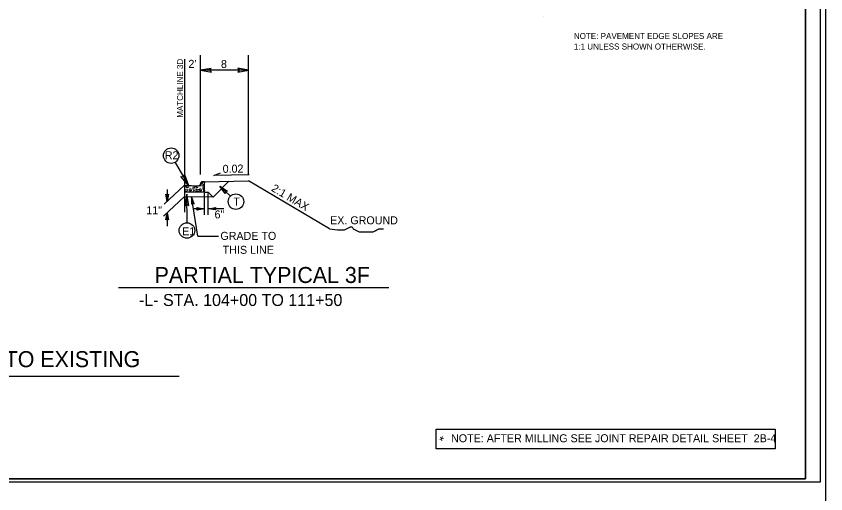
# Model space of a CAD drawing. Extents: x 2320980 to 2456309, y 595047 to 606177.
# Drawn here: x 2455910.9 to 2456045.5, y 596743.6 to 596823 of the extents above; entities that cross this region are included whole.
import ezdxf

# ---------------------------------------------------------------- set-up
doc = ezdxf.new("R2010")
doc.units = 0
for name, color, linetype in [('Matchline', 7, 'Continuous'), ('Matchline Text', 7, 'Continuous'), ('Old_Level_1', 7, 'Continuous'), ('Old_Level_2', 7, 'Continuous'), ('Old_Level_20', 7, 'Continuous'), ('Old_Level_21', 7, 'Continuous'), ('Old_Level_3', 7, 'Continuous'), ('Prop Dimension', 7, 'Continuous'), ('Prop Dimension Text', 7, 'Continuous'), ('Prop Pavement Schedule Description CELL', 7, 'Continuous'), ('Prop Terminator CELL', 7, 'Continuous'), ('Sheet Plan CELL', 7, 'Continuous'), ('Sheet Plot Border Inside CELL', 7, 'Continuous'), ('Sheet Plot Border Outside CELL', 7, 'Continuous'), ('Typical Berm CELL', 7, 'Continuous'), ('Typical Curb CELL', 7, 'Continuous'), ('Typical Hinge Slope Arterial CELL', 7, 'Continuous'), ('Typical ID Circle CELL', 7, 'Continuous'), ('Typical Pavement Slope CELL', 7, 'Continuous'), ('Typical Pavement Slope Information CELL', 7, 'Continuous'), ('Typical Terminator CELL', 7, 'Continuous')]:
    doc.layers.add(name, color=color, linetype=linetype)

msp = doc.modelspace()

# ---------------------------------------------------------------- linework, layer by layer
at = {"layer": 'Matchline'}
msp.add_line((2455938.91, 596815.85), (2455938.91, 596790.41), dxfattribs=at)
at = {"layer": 'Old_Level_21'}
for p, q in [((2455941.57, 596812.79), (2455941.57, 596816.52)), ((2455949.57, 596796.71), (2455949.57, 596816.52)), ((2455949.57, 596814.03), (2455941.57, 596814.03)), ((2455941.57, 596796.71), (2455941.57, 596812.79)), ((2455963.04, 596787.65), (2455949.57, 596795.62)), ((2455941.13, 596786.4), (2455940.1, 596793.02)), ((2455942.24, 596789.98), (2455942.24, 596793.57)), ((2455942.87, 596789.98), (2455942.87, 596793.53)), ((2455941.13, 596786.4), (2455944.57, 596786.4))]:
    msp.add_line(p, q, dxfattribs=at)
msp.add_lwpolyline([(2455980.74, 596754.3), (2456037.11, 596754.3), (2456037.11, 596751.08), (2455980.74, 596751.08)], close=True, dxfattribs=at)
at = {"layer": 'Old_Level_3'}
for p, q in [((2455927.96, 596777.91), (2455972.88, 596777.91)), ((2455830.01, 596763.14), (2455938.01, 596763.14))]:
    msp.add_line(p, q, dxfattribs=at)
at = {"layer": 'Prop Dimension'}
for p, q in [((2455938.91, 596794.91), (2455935.54, 596791.73)), ((2455938.92, 596793.04), (2455935.41, 596789.73)), ((2455936.04, 596794.2), (2455936.04, 596792.2)), ((2455936.04, 596790.33), (2455936.04, 596788.07))]:
    msp.add_line(p, q, dxfattribs=at)
at = {"layer": 'Prop Dimension Text'}
for p, q in [((2455946.54, 596793.07), (2455944.78, 596794.75)), ((2455942.24, 596791), (2455940.35, 596791)), ((2455945.43, 596791), (2455942.87, 596791))]:
    msp.add_line(p, q, dxfattribs=at)
msp.add_lwpolyline([(2455949.64, 596796.65), (2455943.78, 596796.49), (2455944.92, 596796.98)], dxfattribs=at)
for centre in [(2455936.7, 596799.82), (2455947.47, 596792.17), (2455939.32, 596787.37)]:
    msp.add_circle(centre, 1.29, dxfattribs=at)
at = {"layer": 'Prop Pavement Schedule Description CELL'}
msp.add_line((2455998.64, 596823.01), (2455998.64, 596823.01), dxfattribs=at)
at = {"layer": 'Prop Terminator CELL'}
for points in [[(2455936.24, 596793.4), (2455936.04, 596792.2), (2455935.82, 596793.41), (2455936.04, 596793.25)], [(2455935.83, 596789.13), (2455936.04, 596790.33), (2455936.25, 596789.12), (2455936.04, 596789.28)]]:
    msp.add_lwpolyline(points, close=True, dxfattribs=at)
at = {"layer": 'Sheet Plan CELL'}
for points in [[(2456042.11, 596956.08), (2455742.1, 596956.08), (2455742.1, 596746.08), (2456042.11, 596746.08)], [(2455742.1, 596746.08), (2455742.1, 596956.07), (2456002.1, 596956.08), (2456002.1, 596926.07), (2456042.11, 596926.06), (2456042.11, 596746.08)]]:
    msp.add_lwpolyline(points, close=True, dxfattribs=at)
at = {"layer": 'Sheet Plot Border Inside CELL'}
msp.add_lwpolyline([(2455711.41, 596745.57), (2456044.6, 596745.58), (2456044.61, 596956.57), (2455711.41, 596956.57)], close=True, dxfattribs=at)
at = {"layer": 'Sheet Plot Border Outside CELL'}
msp.add_lwpolyline([(2455708.81, 596741.57), (2456045.51, 596741.57), (2456045.51, 596960.57), (2455708.81, 596960.57)], close=True, dxfattribs=at)
at = {"layer": 'Typical Berm CELL'}
for p, q in [((2455942.24, 596795.47), (2455949.57, 596795.62)), ((2455942.24, 596793.75), (2455942.86, 596793.75))]:
    msp.add_line(p, q, dxfattribs=at)
at = {"layer": 'Typical Curb CELL'}
for p, q in [((2455938.91, 596794.91), (2455941.24, 596794.82)), ((2455939.26, 596794.46), (2455939.38, 596794.62)), ((2455939.42, 596794.46), (2455939.26, 596794.46)), ((2455939.38, 596794.62), (2455939.42, 596794.46)), ((2455940.28, 596794.39), (2455940.36, 596794.54)), ((2455940.5, 596794.44), (2455940.28, 596794.39)), ((2455940.36, 596794.54), (2455940.5, 596794.44)), ((2455940.92, 596794.46), (2455941.04, 596794.62)), ((2455941.08, 596794.46), (2455940.92, 596794.46)), ((2455941.04, 596794.62), (2455941.08, 596794.46)), ((2455941.57, 596795.13), (2455941.57, 596795.15)), ((2455941.69, 596795.12), (2455941.77, 596795.27)), ((2455941.91, 596795.17), (2455941.69, 596795.12)), ((2455941.77, 596795.27), (2455941.91, 596795.17)), ((2455942.24, 596795.47), (2455941.89, 596795.47)), ((2455941.94, 596794.39), (2455942.02, 596794.54)), ((2455942.16, 596794.44), (2455941.94, 596794.39)), ((2455941.99, 596795.02), (2455942.01, 596794.9)), ((2455942.19, 596794.96), (2455941.99, 596795.02)), ((2455942.01, 596794.9), (2455942.19, 596794.96)), ((2455942.02, 596794.54), (2455942.16, 596794.44)), ((2455942.24, 596793.75), (2455942.24, 596795.47)), ((2455942.24, 596793.75), (2455938.91, 596793.75)), ((2455939.05, 596793.86), (2455939.16, 596794.01)), ((2455939.21, 596793.86), (2455939.05, 596793.86)), ((2455939.16, 596794.01), (2455939.21, 596793.86)), ((2455939.84, 596793.95), (2455939.95, 596794.11)), ((2455940, 596793.96), (2455939.84, 596793.95)), ((2455939.95, 596794.11), (2455940, 596793.96)), ((2455940.86, 596793.88), (2455940.94, 596794.03)), ((2455941.08, 596793.93), (2455940.86, 596793.88)), ((2455940.94, 596794.03), (2455941.08, 596793.93)), ((2455941.5, 596793.95), (2455941.61, 596794.11)), ((2455941.66, 596793.96), (2455941.5, 596793.95)), ((2455941.61, 596794.11), (2455941.66, 596793.96))]:
    msp.add_line(p, q, dxfattribs=at)
for centre in [(2455938.94, 596794.59), (2455938.96, 596794.71), (2455939.01, 596794.4), (2455939.03, 596794.67), (2455939.14, 596794.46), (2455939.18, 596794.84), (2455939.31, 596794.72), (2455939.37, 596794.86), (2455939.57, 596794.77), (2455939.6, 596794.64), (2455939.8, 596794.53), (2455939.84, 596794.75), (2455939.85, 596794.32), (2455939.86, 596794.82), (2455939.97, 596794.56), (2455940.2, 596794.78), (2455940.36, 596794.71), (2455940.6, 596794.59), (2455940.62, 596794.71), (2455940.67, 596794.4), (2455940.69, 596794.67), (2455940.8, 596794.46), (2455940.84, 596794.78), (2455940.97, 596794.72), (2455941.23, 596794.77), (2455941.26, 596794.64), (2455941.46, 596794.53), (2455941.5, 596794.75), (2455941.51, 596794.32), (2455941.52, 596794.82), (2455941.63, 596794.56), (2455941.65, 596794.99), (2455941.81, 596794.93), (2455941.86, 596794.78), (2455941.93, 596795.37), (2455942.02, 596794.71), (2455942.15, 596795.08), (2455942.22, 596795.32), (2455938.93, 596794.18), (2455939.13, 596794.08), (2455939.21, 596794.15), (2455939.37, 596794.16), (2455939.39, 596794.04), (2455939.42, 596794.24), (2455939.69, 596794.21), (2455939.72, 596793.95), (2455939.92, 596794.17), (2455940.16, 596794.25), (2455940.18, 596794.13), (2455940.38, 596794.2), (2455940.38, 596794.02), (2455940.42, 596793.81), (2455940.55, 596794.05), (2455940.59, 596794.18), (2455940.87, 596794.15), (2455940.94, 596794.21), (2455941.08, 596794.24), (2455941.18, 596794.08), (2455941.2, 596794.21), (2455941.25, 596793.89), (2455941.27, 596794.16), (2455941.36, 596794.21), (2455941.38, 596793.95), (2455941.58, 596794.17), (2455941.82, 596794.25), (2455941.84, 596794.13), (2455942.04, 596794.02), (2455942.05, 596794.2), (2455942.08, 596793.81), (2455942.21, 596794.05)]:
    msp.add_circle(centre, 0.0107, dxfattribs=at)
for centre, start, end in [((2455941.26, 596795.13), 267.6155, 360), ((2455941.89, 596795.15), 90, 180)]:
    msp.add_arc(centre, 0.319, start, end, dxfattribs=at)
at = {"layer": 'Typical Hinge Slope Arterial CELL'}
msp.add_lwpolyline([(2455963.04, 596787.65), (2455964.35, 596787.48), (2455964.68, 596787.48), (2455965.17, 596787.48), (2455965.5, 596787.48), (2455965.82, 596787.65), (2455966.15, 596787.81), (2455966.48, 596787.97), (2455966.81, 596787.97), (2455966.97, 596787.65), (2455967.3, 596787.48), (2455967.63, 596787.32), (2455967.95, 596787.16), (2455968.28, 596787.16), (2455968.61, 596787.16), (2455968.94, 596787.16), (2455969.26, 596787.16), (2455969.59, 596787.16), (2455969.92, 596787.16), (2455970.25, 596787.16), (2455970.58, 596787.32), (2455970.9, 596787.48), (2455971.23, 596787.65), (2455971.72, 596787.65), (2455971.99, 596787.65)], dxfattribs=at)
at = {"layer": 'Typical ID Circle CELL'}
for p, q in [((2455937.34, 596798.7), (2455939.57, 596794.88)), ((2455939.34, 596788.67), (2455939.31, 596793.39))]:
    msp.add_line(p, q, dxfattribs=at)
at = {"layer": 'Typical Pavement Slope CELL'}
for p, q in [((2455938.91, 596794.91), (2455938.91, 596793.75)), ((2455946.28, 596795.55), (2455943.67, 596792.94)), ((2455938.91, 596793.04), (2455943.67, 596792.95)), ((2455942.86, 596793.75), (2455943.67, 596792.94))]:
    msp.add_line(p, q, dxfattribs=at)
at = {"layer": 'Typical Terminator CELL'}
for points in [[(2455943.37, 596814.34), (2455941.57, 596814.03), (2455943.38, 596813.71), (2455943.15, 596814.03)], [(2455947.78, 596813.72), (2455949.57, 596814.03), (2455947.77, 596814.35), (2455948, 596814.03)], [(2455938.9, 596796.68), (2455939.57, 596794.88), (2455938.32, 596796.36), (2455938.73, 596796.32)], [(2455945.68, 596793.53), (2455944.78, 596794.75), (2455946.05, 596793.9), (2455945.73, 596793.84)], [(2455939.65, 596791.5), (2455939.31, 596793.39), (2455938.99, 596791.48), (2455939.32, 596791.73)], [(2455940.5, 596791.82), (2455940.1, 596793.02), (2455940.07, 596791.74), (2455940.27, 596791.94)], [(2455940.99, 596791.21), (2455942.24, 596791), (2455940.99, 596790.77), (2455941.14, 596791)], [(2455944.12, 596790.78), (2455942.87, 596791), (2455944.13, 596791.22), (2455943.97, 596791)]]:
    msp.add_lwpolyline(points, close=True, dxfattribs=at)

# ---------------------------------------------------------------- texts
at = {"layer": 'Matchline Text'}
msp.add_text('MATCHLINE 3D', height=1, rotation=90, dxfattribs=at).set_placement((2455938.67, 596806.12))
at = {"layer": 'Old_Level_1'}
msp.add_text('EX. GROUND', height=1.33, rotation=359.9103, dxfattribs=at).set_placement((2455963.12, 596788.41))
at = {"layer": 'Old_Level_2'}
for s, height, p in [('PARTIAL TYPICAL 3F', 2.66, (2455933.95, 596778.64)), ('-L- STA. 104+00 TO 111+50', 1.995, (2455931.34, 596774.81)), ('TRANSITION FROM TYPICAL SECTION No. 3 TO EXISTING', 2.66, (2455832.94, 596764.64))]:
    msp.add_text(s, height=height, dxfattribs=at).set_placement(p)
at = {"layer": 'Old_Level_20'}
for s, p in [('R2', (2455935.64, 596799.22)), ('T', (2455947.04, 596791.51)), ('E1', (2455938.53, 596786.57))]:
    msp.add_text(s, height=1.33, dxfattribs=at).set_placement(p)
at = {"layer": 'Old_Level_21'}
for s, rotation, p in [("2'", 0.0002, (2455939.57, 596814.42)), ('0.02', 1.1456, (2455945.27, 596796.95)), ('2:1 MAX', 329.3616, (2455953.23, 596794.04))]:
    msp.add_text(s, height=1.33, rotation=rotation, dxfattribs=at).set_placement(p)
for s, p in [('8', (2455944.98, 596814.4)), ('6"', (2455943.91, 596789.38)), ('GRADE TO', (2455944.88, 596785.81)), ('THIS LINE', (2455945.27, 596783.49)), ('NOTE: AFTER MILLING SEE JOINT REPAIR DETAIL SHEET  2B-4', (2455983.22, 596752.15))]:
    msp.add_text(s, height=1.33, dxfattribs=at).set_placement(p)
at = {"layer": 'Prop Pavement Schedule Description CELL'}
for s, p in [('NOTE: PAVEMENT EDGE SLOPES ARE', (2456003.63, 596819.22)), ('1:1 UNLESS SHOWN OTHERWISE.', (2456003.63, 596817.47))]:
    msp.add_text(s, height=0.9998, dxfattribs=at).set_placement(p)
at = {"layer": 'Typical Pavement Slope CELL'}
msp.add_text('*', height=1.5, rotation=333.4341, dxfattribs=at).set_placement((2455980.82, 596751.96))
at = {"layer": 'Typical Pavement Slope Information CELL'}
msp.add_text('11"', height=1.33, dxfattribs=at).set_placement((2455932.57, 596790.07))

doc.saveas('drawing.dxf')
